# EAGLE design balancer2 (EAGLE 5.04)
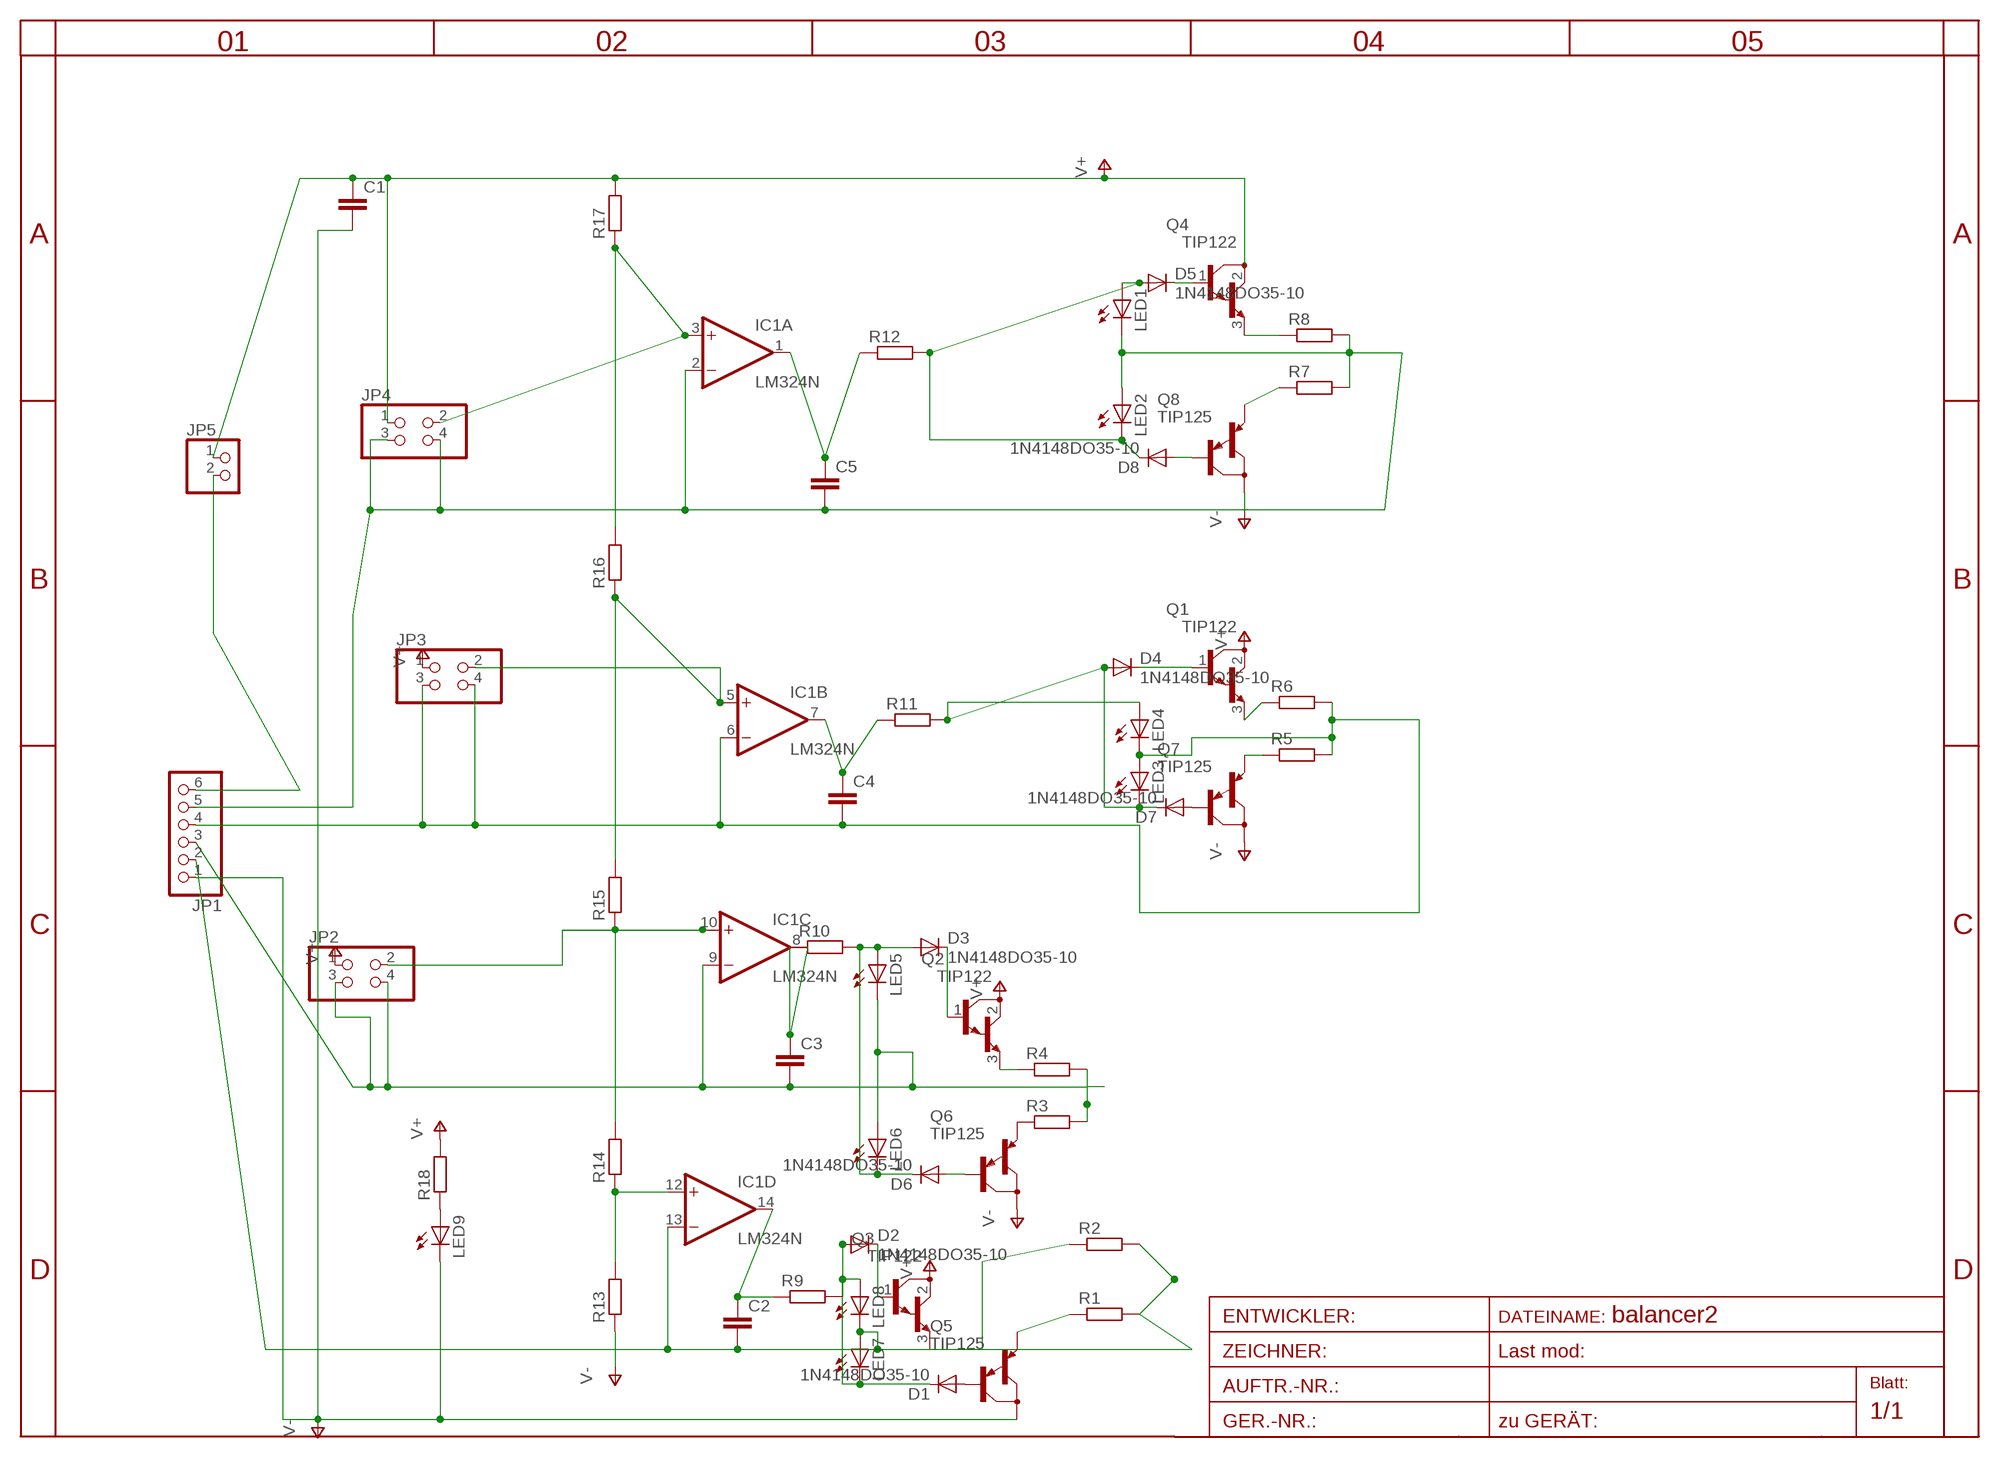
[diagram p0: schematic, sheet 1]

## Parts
C1  C-EU025-024X044  [C025-024X044]
C2  C-EU025-024X044  [C025-024X044]
C3  C-EU025-024X044  [C025-024X044]
C4  C-EU025-024X044  [C025-024X044]
C5  C-EU025-024X044  [C025-024X044]
D1  1N4148DO35-10  [DO35-10]
D2  1N4148DO35-10  [DO35-10]
D3  1N4148DO35-10  [DO35-10]
D4  1N4148DO35-10  [DO35-10]
D5  1N4148DO35-10  [DO35-10]
D6  1N4148DO35-10  [DO35-10]
D7  1N4148DO35-10  [DO35-10]
D8  1N4148DO35-10  [DO35-10]
IC1  LM324N  [DIL14]
JP1  PINHD-1X6  [1X06]
JP2  PINHD-2X2  [2X02]
JP3  PINHD-2X2  [2X02]
JP4  PINHD-2X2  [2X02]
JP5  PINHD-1X2  [1X02]
LED1  LED3MM  [LED3MM]
LED2  LED3MM  [LED3MM]
LED3  LED3MM  [LED3MM]
LED4  LED3MM  [LED3MM]
LED5  LED3MM  [LED3MM]
LED6  LED3MM  [LED3MM]
LED7  LED3MM  [LED3MM]
LED8  LED3MM  [LED3MM]
LED9  LED3MM  [LED3MM]
Q1  TIP122  [TO220]
Q2  TIP122  [TO220]
Q3  TIP122  [TO220]
Q4  TIP122  [TO220]
Q5  TIP125  [TO220]
Q6  TIP125  [TO220]
Q7  TIP125  [TO220]
Q8  TIP125  [TO220]
R1  R-EU_0207/10  [0207/10]
R2  R-EU_0207/10  [0207/10]
R3  R-EU_0207/10  [0207/10]
R4  R-EU_0207/10  [0207/10]
R5  R-EU_0207/10  [0207/10]
R6  R-EU_0207/10  [0207/10]
R7  R-EU_0207/10  [0207/10]
R8  R-EU_0207/10  [0207/10]
R9  R-EU_0207/10  [0207/10]
R10  R-EU_0207/10  [0207/10]
R11  R-EU_0204/5  [0204/5]
R12  R-EU_0207/10  [0207/10]
R13  R-EU_0204/5  [0204/5]
R14  R-EU_0204/5  [0204/5]
R15  R-EU_0204/5  [0204/5]
R16  R-EU_0204/5  [0204/5]
R17  R-EU_0204/5  [0204/5]
R18  R-EU_0204/5  [0204/5]

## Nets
N$1: D1.A Q5.1(B)
N$2: D2.C Q3.1(B)
N$3: D3.C Q2.1(B)
N$4: D4.C Q1.1(B)
N$5: D5.C Q4.1(B)
N$6: D6.A Q6.1(B)
N$7: D7.A Q7.1(B)
N$8: D8.A Q8.1(B)
N$9: D1.C D2.A LED7.K(C) LED8.A R9.2
N$10: D3.A D6.C LED5.A LED6.K(C) R10.2
N$11: D4.A D7.C LED3.K(C) LED4.A R11.2
N$12: D5.A D8.C LED1.A LED2.K(C) R12.2
N$13: Q5.3(E) R1.1
N$14: Q7.3(E) R5.1
N$15: Q1.3(E) R6.1
N$16: Q6.3(E) R3.1
N$17: Q2.3(E) R4.1
N$18: Q4.3(E) R8.1
N$19: Q8.3(E) R7.1
N$20: C5.1 IC1.1(A:OUT) R12.1
N$21: C4.1 IC1.7(B:OUT) R11.1
N$22: IC1.5(B:+IN) JP3.2 R15.2 R16.1
N$23: IC1.3(A:+IN) JP4.2 R16.2 R17.1
N$24: C3.1 IC1.8(C:OUT) R10.1
N$25: C2.1 IC1.14(D:OUT) R9.1
N$26: IC1.10(C:+IN) JP2.2 R14.2 R15.1
N$27: Q3.3(E) R2.1
N$28: IC1.12(D:+IN) R13.2 R14.1
N$29: JP1.6 JP5.2
N$30: C5.2 IC1.2(A:-IN) JP1.5 JP4.3 JP4.4 LED1.K(C) LED2.A R7.2 R8.2
N$33: C3.2 IC1.9(C:-IN) JP1.3 JP2.3 JP2.4 LED5.K(C) LED6.A R3.2 R4.2
N$34: LED9.A R18.1
N$38: C4.2 IC1.6(B:-IN) JP1.4 JP3.3 JP3.4 LED3.A LED4.K(C) R5.2 R6.2
N$39: C2.2 IC1.13(D:-IN) JP1.2 LED7.A LED8.K(C) R1.2 R2.2
V+: C1.1 JP2.1 JP3.1 JP4.1 JP5.1 Q1.2(C) Q2.2(C) Q3.2(C) Q4.2(C) R17.2 R18.2
V-: C1.2 JP1.1 LED9.K(C) Q5.2(C) Q6.2(C) Q7.2(C) Q8.2(C) R13.1

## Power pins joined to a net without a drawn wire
V+: IC1.4(P:V+)
V-: IC1.11(P:V-)

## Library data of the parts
C1-C5 = rcl-2:C-EU: CAPACITOR, European symbol
D1-D8 = diode-1:1N4148: DIODE
IC1 = linear:LM324: OP AMP
JP1 = pinhead:PINHD-1X6: PIN HEADER
JP2-JP4 = pinhead:PINHD-2X2: PIN HEADER
JP5 = pinhead:PINHD-1X2: PIN HEADER
LED1-LED9 = led:LED: LED
Q1-Q4 = transistor-npn:TIP122*: NPN Darlington Transistor
Q5-Q8 = transistor-pnp:TIP125: PNP Transistor
R1-R18 = rcl-2:R-EU_: RESISTOR, European symbol

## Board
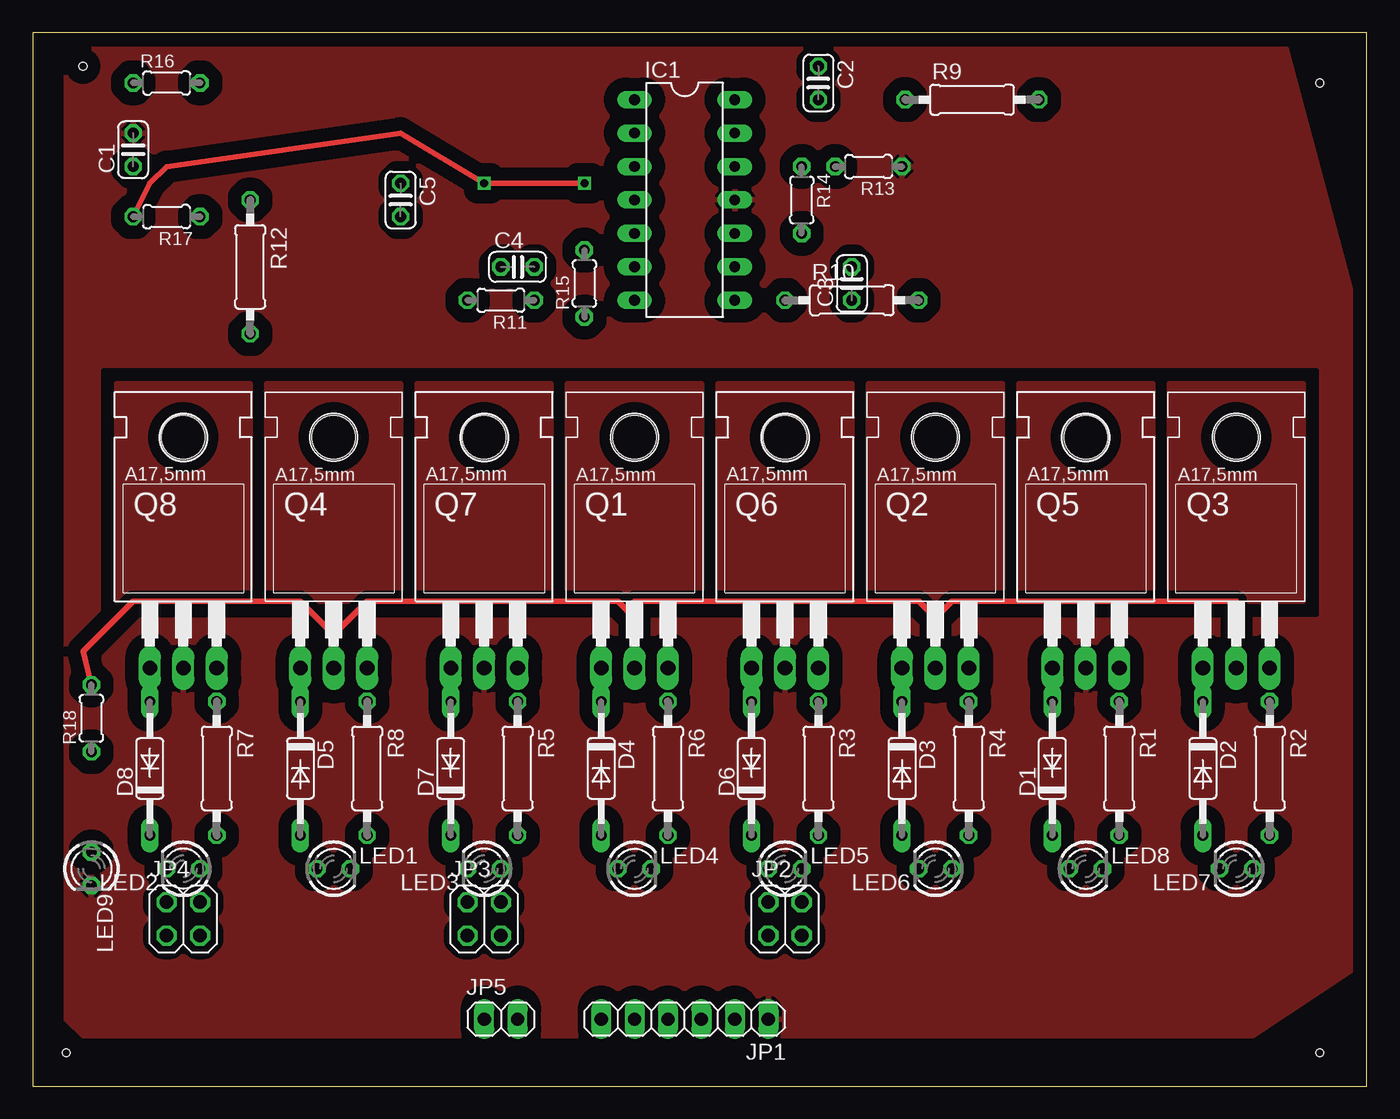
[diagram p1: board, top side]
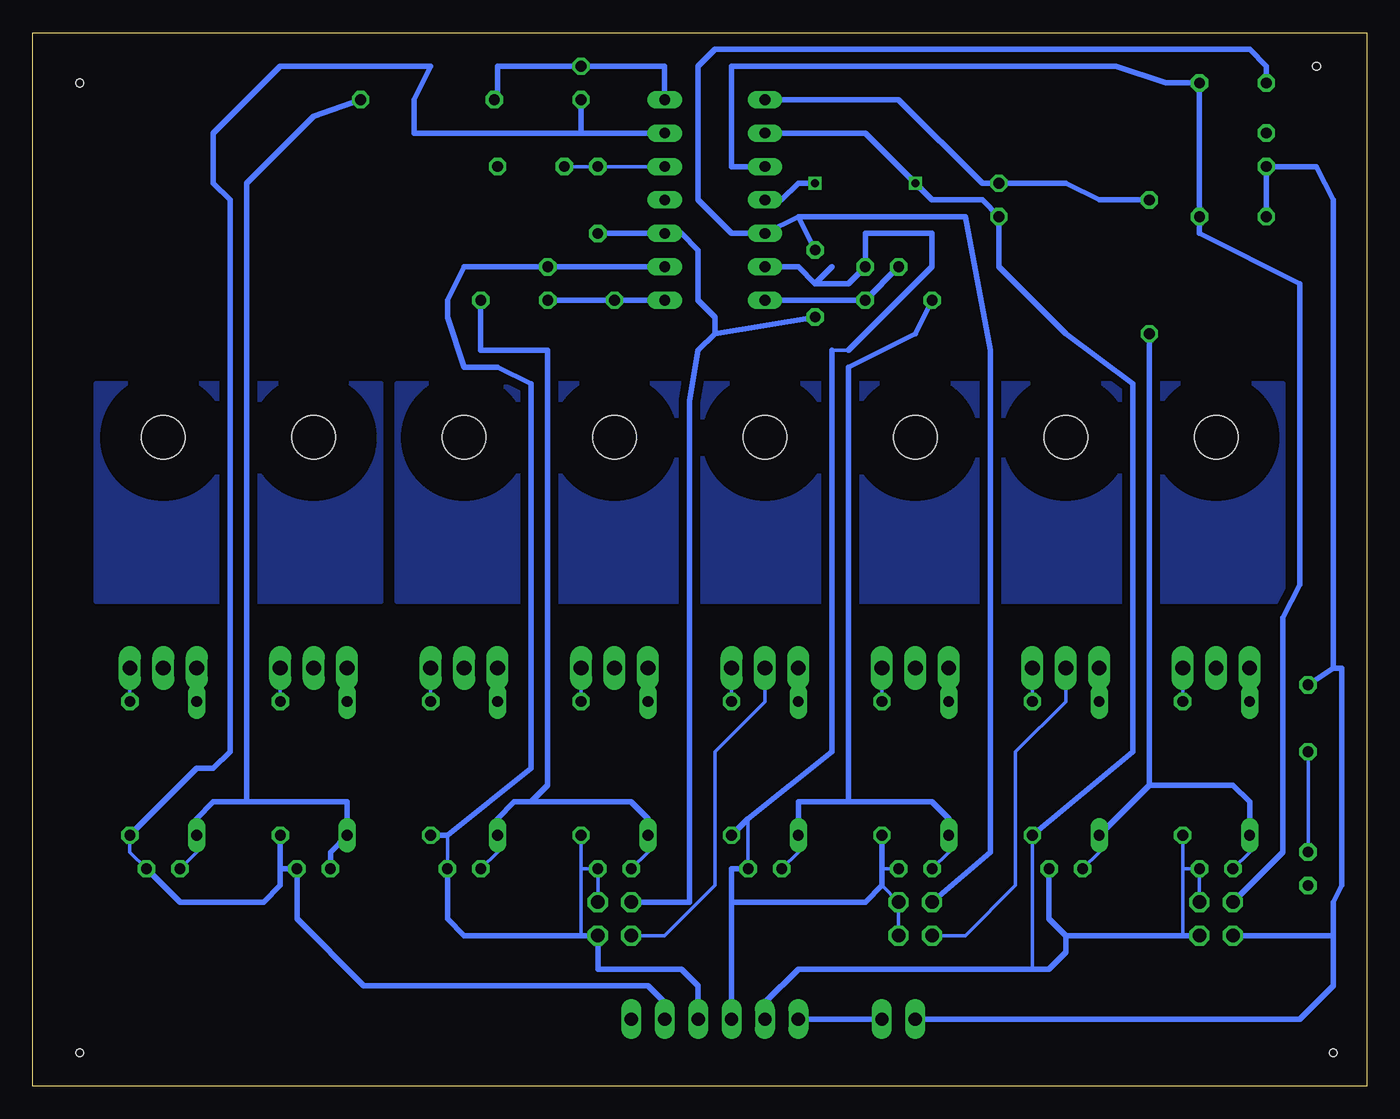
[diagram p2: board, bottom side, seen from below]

Size 101.35 x 80 mm. Coordinates in mm from the lower left corner, seen from the top.
Outline: 0,0 101.35,0 101.35,80 0,80 0,0
Copper layers (1*16): Top 0.035mm / dielectric 1.5mm / Bottom 0.035mm
Design rules "default": minimum track width 10mil, minimum drill 24mil, track to track 8mil, track to pad 8mil, pad to pad 8mil, via to via 8mil, smd to smd 8mil, copper to edge 40mil, drill to drill 8mil, minimum pad ring 10mil, minimum via ring 8mil, stop-mask expansion 4mil, vias tented up to drill 0mil, thermal gap 10mil
Holes 0.6 mm at 2.54,2.54 97.79,2.54 97.79,76.2 3.81,77.47

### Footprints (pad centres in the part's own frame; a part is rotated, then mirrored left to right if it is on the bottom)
C025-024X044 = drill 0.813 octagon: 1 -1.27,0; 2 1.27,0
DO35-10 = drill 0.813 long: A 5.08,0; C -5.08,0
DIL14 = drill 0.813 long: 1 -7.62,-3.81; 2 -5.08,-3.81; 3 -2.54,-3.81; 4 0,-3.81; 5 2.54,-3.81; 6 5.08,-3.81; 7 7.62,-3.81; 8 7.62,3.81; 9 5.08,3.81; 10 2.54,3.81; 11 0,3.81; 12 -2.54,3.81; 13 -5.08,3.81; 14 -7.62,3.81
1X06 = drill 1.016 long: 1 -6.35,0; 2 -3.81,0; 3 -1.27,0; 4 1.27,0; 5 3.81,0; 6 6.35,0
2X02 = drill 1.016 octagon: 1 -1.27,-1.27; 2 -1.27,1.27; 3 1.27,-1.27; 4 1.27,1.27
1X02 = drill 1.016 long: 1 -1.27,0; 2 1.27,0
LED3MM = drill 0.813 octagon: A -1.27,0; K 1.27,0
TO220 = drill 1.118 long: 1 -2.54,-6.35; 2 0,-6.35; 3 2.54,-6.35 | hole 3.302: 0,11.176
0207/10 = drill 0.813 octagon: 1 -5.08,0; 2 5.08,0
0204/5 = drill 0.813 octagon: 1 -2.54,0; 2 2.54,0

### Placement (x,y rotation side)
C1  7.62,71.12 90 top
C2  59.69,76.2 270 top
C3  62.23,60.96 90 top
C4  36.83,62.23 0 top
C5  27.94,67.31 270 top
D1  77.47,24.13 90 top
D2  88.9,24.13 270 top
D3  66.04,24.13 270 top
D4  43.18,24.13 270 top
D5  20.32,24.13 270 top
D6  54.61,24.13 90 top
D7  31.75,24.13 90 top
D8  8.89,24.13 90 top
IC1  49.53,67.31 270 top
JP1  49.53,5.08 180 top
JP2  57.15,12.7 0 top
JP3  34.29,12.7 0 top
JP4  11.43,12.7 0 top
JP5  35.56,5.08 0 top
LED1  22.86,16.51 0 top
LED2  11.43,16.51 180 top
LED3  34.29,16.51 180 top
LED4  45.72,16.51 0 top
LED5  57.15,16.51 0 top
LED6  68.58,16.51 180 top
LED7  91.44,16.51 180 top
LED8  80.01,16.51 0 top
LED9  4.45,16.51 270 top
Q1  45.72,38.1 0 top
Q2  68.58,38.1 0 top
Q3  91.44,38.1 0 top
Q4  22.86,38.1 0 top
Q5  80.01,38.1 0 top
Q6  57.15,38.1 0 top
Q7  34.29,38.1 0 top
Q8  11.43,38.1 0 top
R1  82.55,24.13 270 top
R2  93.98,24.13 270 top
R3  59.69,24.13 270 top
R4  71.12,24.13 270 top
R5  36.83,24.13 270 top
R6  48.26,24.13 270 top
R7  13.97,24.13 270 top
R8  25.4,24.13 270 top
R9  71.36,74.93 0 top
R10  62.23,59.69 0 top
R11  35.56,59.69 180 top
R12  16.51,62.23 270 top
R13  63.5,69.85 180 top
R14  58.42,67.31 270 top
R15  41.91,60.96 90 top
R16  10.16,76.2 0 top
R17  10.16,66.04 180 top
R18  4.45,27.94 90 top

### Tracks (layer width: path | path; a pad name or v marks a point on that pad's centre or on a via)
N$1
  Bottom 0.254: D1.A Q5.1
N$2
  Bottom 0.254: D2.C Q3.1
N$3
  Bottom 0.254: D3.C Q2.1
N$4
  Bottom 0.254: D4.C Q1.1
N$5
  Bottom 0.254: D5.C Q4.1
N$6
  Bottom 0.254: D6.A Q6.1
N$7
  Bottom 0.254: D7.A Q7.1
N$8
  Bottom 0.254: D8.A Q8.1
N$9
  Bottom 0.254: LED7.K 88.9,17.78 D2.A
  Bottom 0.406: D2.A 88.9,20.32 87.63,21.59 85.09,21.59 | 85.09,21.59 77.47,21.59 D1.C 78.74,17.78 LED8.A | R9.2 80.01,73.66 85.09,68.58 85.09,21.59
N$10
  Bottom 0.254: LED5.A 54.61,17.78 D6.C | LED6.K 66.04,17.78 D3.A
  Bottom 0.406: D6.C 54.61,20.32 55.88,21.59 63.5,21.59 | 63.5,21.59 64.77,21.59 66.04,20.32 D3.A | 63.5,21.59 62.23,22.86 62.23,55.88 67.31,55.88 R10.2
N$11
  Bottom 0.254: LED3.K 31.75,17.78 D7.C | LED4.A 43.18,17.78 D4.A
  Bottom 0.406: D4.A 43.18,21.59 39.37,21.59 | 39.37,21.59 33.02,21.59 31.75,20.32 D7.C | 39.37,21.59 39.37,54.61 34.29,57.15 R11.2
N$12
  Bottom 0.254: LED2.K 8.89,17.78 D8.C | LED1.A 20.32,17.78 D5.A
  Bottom 0.406: 16.51,22.86 10.16,22.86 8.89,21.59 D8.C | 16.51,22.86 D5.A | 16.51,22.86 R12.2
N$13
  Bottom 0.254: R1.1 Q5.3
N$14
  Bottom 0.254: R5.1 Q7.3
N$15
  Bottom 0.254: R6.1 Q1.3
N$16
  Bottom 0.254: R3.1 Q6.3
N$17
  Bottom 0.254: R4.1 Q2.3
N$18
  Bottom 0.254: R8.1 Q4.3
N$19
  Bottom 0.254: R7.1 Q8.3
N$20
  Bottom 0.406: R12.1 20.32,67.31 22.86,68.58 C5.1 29.21,68.58 35.56,74.93 IC1.1
N$21
  Bottom 0.406: C4.1 R11.1 IC1.7
N$22
  Bottom 0.406: JP3.2 28.57,17.78 28.57,55.88 30.48,66.04 43.18,66.04 | 43.18,66.04 IC1.5 48.26,64.77 50.8,67.31 50.8,77.47 49.53,78.74 8.89,78.74 7.62,77.47 R16.1 | 43.18,66.04 R15.2
N$23
  Bottom 0.406: IC1.3 48.26,69.85 48.26,77.47 19.05,77.47 15.24,76.2 R16.2 R17.1 12.7,64.77 5.08,60.96 5.08,38.1 6.35,35.56 6.35,17.78 JP4.2
N$24
  Bottom 0.406: IC1.8 R10.1 C3.1
N$25
  Bottom 0.406: IC1.14 53.34,77.47 C2.1 66.04,77.47 66.04,75.17 R9.1
N$26
  Bottom 0.406: JP2.2 51.44,13.97 51.44,52.07 50.8,55.88 49.53,57.15 | 49.53,57.15 R15.1 | 49.53,57.15 49.53,58.42 50.8,59.69 50.8,63.5 52.07,64.77 IC1.10 R14.2
N$27
  Bottom 0.254: R2.1 Q3.3
N$28
  Bottom 0.254: IC1.12 R14.1 R13.2
N$29
  Bottom 0.406: JP5.2 JP1.6
N$30
  Bottom 0.254: JP4.4 LED2.A 13.97,16.51 | 13.97,11.43 13.97,16.51 | 13.97,16.51 R7.2 | JP1.5 45.72,3.81 | 25.4,8.89 R8.2
  Bottom 0.406: JP1.5 45.72,6.35 43.18,8.89 25.4,8.89 24.13,8.89 22.86,10.16 22.86,11.43 | 22.86,11.43 24.13,12.7 LED1.K | JP4.3 13.97,11.43 22.86,11.43 | R8.2 17.78,25.4 17.78,53.34 22.86,57.15 27.94,62.23 C5.2 29.21,67.31 33.02,67.31 38.1,72.39 IC1.2
N$31
  pour Bottom (isolate 0.61, rank 4): 6.35,53.34 16.51,53.34 16.51,36.83 6.35,36.83
  pour Top (isolate 0.61, rank 4): 6.35,53.34 16.51,53.34 16.51,36.83 6.35,36.83
  pour Top (isolate 0.61, rank 4): 17.78,53.34 27.94,53.34 27.94,36.83 17.78,36.83
  pour Top (isolate 0.61, rank 4): 29.21,53.34 39.37,53.34 39.37,36.83 29.21,36.83
  pour Top (isolate 0.61, rank 4): 40.64,53.34 50.8,53.34 50.8,36.83 40.64,36.83
  pour Top (isolate 0.61, rank 4): 52.07,53.34 62.23,53.34 62.23,36.83 52.07,36.83
  pour Top (isolate 0.61, rank 4): 63.5,53.34 73.66,53.34 73.66,36.83 63.5,36.83
  pour Top (isolate 0.61, rank 4): 74.93,53.34 85.09,53.34 85.09,36.83 74.93,36.83
  pour Top (isolate 0.61, rank 4): 86.36,53.34 96.52,53.34 96.52,36.83 86.36,36.83
  pour Bottom (isolate 0.61, rank 4): 17.78,53.34 27.94,53.34 27.94,36.83 17.78,36.83
  pour Bottom (isolate 0.61, rank 4): 29.21,53.34 39.37,53.34 39.37,36.83 29.21,36.83
  pour Bottom (isolate 0.61, rank 4): 40.64,53.34 50.8,53.34 50.8,36.83 40.64,36.83
  pour Bottom (isolate 0.61, rank 4): 52.07,53.34 62.23,53.34 62.23,36.83 52.07,36.83
  pour Bottom (isolate 0.61, rank 4): 63.5,53.34 73.66,53.34 73.66,36.83 63.5,36.83
  pour Bottom (isolate 0.61, rank 4): 74.93,53.34 85.09,53.34 85.09,36.83 74.93,36.83
  pour Bottom (isolate 0.61, rank 4): 86.36,53.34 96.52,53.34 96.52,36.83 86.36,36.83
N$33
  Bottom 0.254: JP2.4 LED5.K 59.69,16.51 | 59.69,11.43 59.69,16.51 | 59.69,16.51 R3.2 | LED6.A 69.85,19.05
  Bottom 0.406: LED6.A 69.85,12.7 68.58,11.43 59.69,11.43 JP2.3 58.42,8.89 52.07,8.89 50.8,7.62 JP1.3 | R4.2 69.85,19.05 63.5,24.13 63.5,53.34 66.04,54.61 68.58,54.61 69.85,58.42 69.85,59.69 68.58,62.23 C3.2 IC1.9
N$34
  Bottom 0.254: LED9.A R18.1
N$38
  Bottom 0.254: 36.83,16.51 LED3.A | 36.83,15.24 JP3.4 JP3.3 | 40.64,55.88 39.37,55.88 | LED4.K 46.99,20.32
  Bottom 0.406: 48.26,13.97 JP1.4 | 48.26,13.97 48.26,16.51 LED4.K | R5.2 36.83,16.51 36.83,15.24 38.1,13.97 48.26,13.97 | R6.2 46.99,20.32 40.64,25.4 40.64,55.88 | IC1.6 43.18,62.23 41.91,60.96 | 41.91,60.96 40.64,62.23 | 39.37,55.88 33.02,62.23 33.02,64.77 38.1,64.77 C4.2 39.37,60.96 41.91,60.96
N$39
  Bottom 0.254: R2.2 93.98,17.78 LED7.A
  Bottom 0.406: JP1.2 53.34,6.35 54.61,7.62 76.2,7.62 81.28,12.7 LED8.K 82.55,16.51 | 82.55,16.51 82.55,15.24 83.82,13.97 90.17,13.97 LED7.A | 82.55,16.51 R1.2 | R2.2 88.9,24.13 87.63,24.13 86.36,25.4 86.36,67.31 87.63,68.58 87.63,72.39 82.55,77.47 71.12,77.47 72.39,74.93 72.39,72.39 59.69,72.39 | 59.69,72.39 IC1.13 | 59.69,72.39 C2.2
V+  (via drill 0.6)
  Top 0.406: R18.2 3.81,33.02 7.62,36.83 20.32,36.83 22.86,34.29 | 22.86,34.29 Q4.2 | 22.86,34.29 25.4,36.83 44.45,36.83 45.72,35.56 Q1.2 45.72,36.83 67.31,36.83 68.58,35.56 | 68.58,35.56 Q2.2 | Q3.2 91.44,36.83 69.85,36.83 68.58,35.56 | R17.2 8.89,68.58 10.16,69.85 27.94,72.39 v34.29,68.58 v41.91,68.58
  Bottom 0.254: 44.45,67.31 IC1.4 | JP3.1 30.48,11.43 26.67,15.24 26.67,25.4 22.86,29.21 Q4.2 | JP2.1 53.34,11.43 49.53,15.24 49.53,25.4 45.72,29.21 Q1.2
  Bottom 0.406: JP5.1 5.08,5.08 2.54,7.62 2.54,11.43 | 2.54,11.43 2.54,13.97 1.91,15.24 1.91,31.75 2.54,31.75 | 2.54,31.75 R18.2 | 2.54,11.43 JP4.1 | 2.54,31.75 2.54,67.31 3.81,69.85 C1.1 R17.2 | v41.91,68.58 43.18,68.58 44.45,67.31
V-
  pour Top (isolate 1.016, rank 5): 2.54,78.74 95.25,78.74 100.33,59.69 100.33,8.89 92.71,3.81 3.81,3.81 2.54,5.08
